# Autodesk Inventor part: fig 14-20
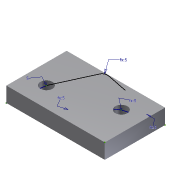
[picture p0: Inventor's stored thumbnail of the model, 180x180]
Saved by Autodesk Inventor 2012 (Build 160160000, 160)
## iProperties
Created: 2005-04
Part Number: fig 14-20
Document SubType Name: Modeling
Designer: CADCIM
Density: 1 g/cm^3
Material: Default
Author: CADCIM
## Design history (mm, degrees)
sketch "Sketch1"
  geometry: L1 (-34.758, -22.218)-(30.545, -22.218); L2 (30.545, -22.218)-(30.545, 17.782); L3 (30.545, 17.782)-(-34.758, 17.782); L4 (-34.758, 17.782)-(-34.758, -22.218)
  constraints: 8 end point, 2 parallel, 1 horizontal, 1 perpendicular
  dimensions: "d0" = 65.30359 distance of L2.end L3.end; "d1" = 40 distance of L1.end L2.end
extrude "Extrusion1" new body sketch "Sketch1" distance "d2" = 10; taper "d3" = 0 deg
hole "Hole1" diameter "d13" = 8; stored, may be unused: countersink angle "d17" = 90 deg, drill point angle "d19" = 118 deg; dims "d11" = 13.458, "d12" = 13.14, "d14" = 6, "d15" = 4, "d16" = 2, "d18" = 15
hole "Hole2" diameter "d22" = 8; stored, may be unused: countersink angle "d26" = 90 deg, drill point angle "d28" = 118 deg; dims "d20" = 13.299, "d21" = 15.705, "d23" = 6, "d24" = 4, "d25" = 2, "d27" = 15
sketch "3D Sketch2" dims "d29" = 5, "d30" = 5 (= d29), "d31" = 5 (= d29), "d32" = 5 (= d29), "d33" = 5 (= d29)
body "Solid1"
other parameters: "LEN" = 1 [user parameter]
